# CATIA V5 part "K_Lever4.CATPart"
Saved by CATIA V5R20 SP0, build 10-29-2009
Part number: Lever
Bounding box of the stored display mesh (mm): x -12.5 to 12.5, y 73.627 to 92.225, z 19.659 to 36.335
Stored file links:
  G:\Khaled_CFAO_2011\SIL\SIL_GR2\ctanaphiko\Khaled\CAD_ThinkMOTION\K_Lever4.CATPart
  G:\Khaled_CFAO_2011\SIL\SIL_GR2\ctanaphiko\CATIA\ctanaphiko.CATProduct
  G:\Khaled_CFAO_2011\SIL\SIL_GR2\ctanaphiko\Khaled\CAD_ThinkMOTION\K_Part4.CATPart
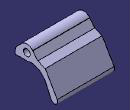
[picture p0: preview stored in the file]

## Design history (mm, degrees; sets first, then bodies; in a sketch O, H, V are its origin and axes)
External parameters (linked from other documents)
  External.Width_Leg_Support = 75 mm
  External.Width_Leg_Support.1 = 75 mm
AxisSystem1: origin (0, 0, 0), X (1, 0, 0), Y (0, 1, 0), Z (0, 0, 1)
Set1
  Plane1: linked copy from another document
Body1 (main body)
  Sketch1 on YZ plane of AxisSystem1, origin (0, 0, 0), H (0, 1, 0), V (0, 0, 1)
    arc A1 centre (78.6269, 33.0852) radius 3.25 from (76.3062, 35.3604) to (81.2157, 35.05) cw
    line L1 (76.3062, 35.3604) -> (74.3417, 33.3567)
    line L2 (73.6269, 31.6065) -> (73.6269, 29.9256)
    line L3 (73.6269, 29.9256) -> (77.8655, 29.9256)
    circle A2 centre (78.6269, 33.0852) radius 1.5
    arc A3 centre (76.1269, 31.6065) radius 2.5 from (74.3417, 33.3567) to (73.6269, 31.6065) ccw
    line L4 (81.2652, 34.9875) -> (83.4906, 32.2861)
    line L5 (83.4906, 32.2861) -> (86.7409, 30.988)
    line L6 (86.7409, 30.988) -> (92.0228, 21.9132)
    point P10 (76.9595, 47.7935)
    point P11 (76.9595, 47.7935)
    line L7 (89.3611, 20.5374) -> (86.5174, 26.7872)
    line L8 (86.5174, 26.7872) -> (84.3033, 29.0582)
    line L9 (84.3033, 29.0582) -> (82.3655, 29.8673)
    point P14 (80.6843, 30.5693)
    arc A4 centre (90.7264, 21.1587) radius 1.5 from (89.3611, 20.5374) to (92.0228, 21.9132) ccw
    arc A5 centre (78.6269, 33.0852) radius 3.25 from (79.6119, 29.988) to (77.8655, 29.9256) cw
    arc A6 centre (82.8088, 36.2592) radius 2 from (81.2157, 35.05) to (81.2652, 34.9875) ccw
    arc A7 centre (80.8242, 26.1762) radius 4 from (79.6119, 29.988) to (82.3655, 29.8673) cw
    distance A2 L2 = 3.5
    distance A1 A2 = 1.75 {= Sketch1.distance(A2 L2) *0.5}
    radius A2 = 1.5 {= 1.5mm}
    radius A3 = 2.5
    radius A4 = 1.5 {= Sketch1.radius(A2)}
    radius A6 = 2
    radius A7 = 4
    length L4 = 3.5 {= Sketch1.distance(A2 L2)}
    length L5 = 3.5 {= Sketch1.distance(A2 L2)}
    length L6 = 10.5 {= Sketch1.length(L5) *3}
    length L9 = 2.1 {= Sketch1.distance(A1 A2)*1.2}
    tangency: L1 A1, A3 L1, A3 L2, A4 L7, A4 L6, A6 L4, A6 A1, A7 L9, A7 A5
    vertical: L2 V
    horizontal: L3 H
    coincidence: P14 A1, P11 P10, L7 P11, L6 P10, A1 A5, A5 P14, L9 P14
  Pad1: profile Sketch1, direction (1, 0, 0), length 12.5 {= (External.Width_Leg_Support /3)/2}, mirrored extent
